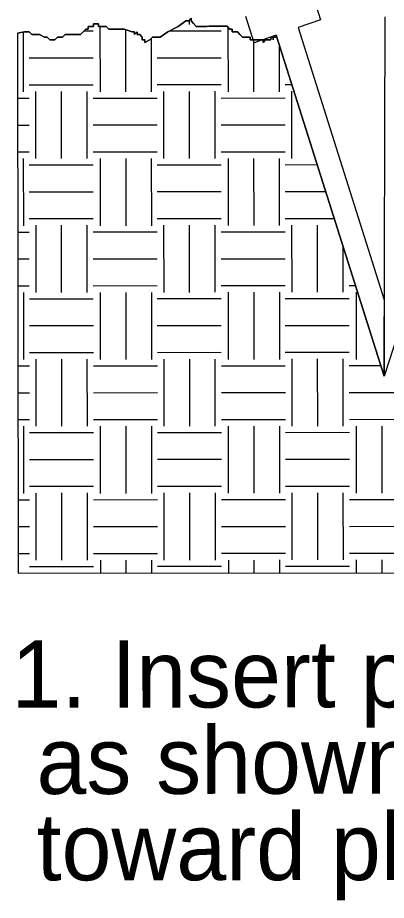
# Model space of a CAD drawing. Extents: x 816132 to 817815, y 885694 to 886789.
# Drawn here: x 816625.1 to 816662, y 886354.3 to 886442.4 of the extents above; entities that cross this region are included whole.
import ezdxf

# ---------------------------------------------------------------- set-up
doc = ezdxf.new("R2010")
doc.units = 0
doc.layers.add('Silt Fence Coir Fiber Wattle Break Detail CELL', color=7, linetype='Continuous')

msp = doc.modelspace()

# ---------------------------------------------------------------- linework, layer by layer
at = {"layer": 'Silt Fence Coir Fiber Wattle Break Detail CELL'}
for p, q in [((816654.546, 886444.801), (816655.377, 886442.179)), ((816648.758, 886439.872), (816647.928, 886442.494)), ((816661.727, 886406.589), (816661.843, 886442.464)), ((816633.353, 886441.513), (816633.358, 886434.979)), ((816642.253, 886442.12), (816642.253, 886441.691)), ((816646.136, 886441.429), (816646.141, 886434.99)), ((816655.377, 886442.179), (816653.15, 886441.403)), ((816625.126, 886440.833), (816625.166, 886386.952)), ((816625.685, 886440.951), (816625.689, 886434.974)), ((816631.755, 886441.059), (816632.667, 886441.059)), ((816635.91, 886441.2), (816635.915, 886434.982)), ((816640.307, 886441.066), (816645.45, 886441.069)), ((816650.951, 886440.637), (816648.758, 886439.872)), ((816661.727, 886406.589), (816650.951, 886440.637)), ((816650.951, 886440.637), (816661.727, 886406.589)), ((816661.727, 886406.589), (816650.951, 886440.637)), ((816653.15, 886441.403), (816661.752, 886414.228)), ((816638.467, 886440.296), (816638.471, 886434.984)), ((816648.693, 886440.179), (816648.697, 886434.992)), ((816651.25, 886439.693), (816651.253, 886434.994)), ((816626.278, 886438.373), (816632.669, 886438.378)), ((816639.06, 886438.383), (816645.451, 886438.389)), ((816626.28, 886435.691), (816632.67, 886435.696)), ((816639.062, 886435.701), (816645.453, 886435.707)), ((816651.845, 886435.712), (816652.51, 886435.712)), ((816626.919, 886435.022), (816626.924, 886428.317)), ((816629.476, 886435.024), (816629.481, 886428.32)), ((816632.032, 886435.025), (816632.037, 886428.322)), ((816632.672, 886434.356), (816639.064, 886434.361)), ((816639.702, 886435.032), (816639.707, 886428.328)), ((816642.258, 886435.033), (816642.263, 886428.33)), ((816644.815, 886435.035), (816644.819, 886428.331)), ((816645.454, 886434.366), (816651.845, 886434.371)), ((816652.484, 886435.041), (816652.489, 886428.338)), ((816625.131, 886434.35), (816626.281, 886434.351)), ((816625.134, 886431.668), (816626.283, 886431.669)), ((816632.674, 886431.674), (816639.065, 886431.679)), ((816645.456, 886431.684), (816651.848, 886431.689)), ((816625.135, 886428.987), (816626.284, 886428.988)), ((816625.693, 886428.317), (816625.698, 886421.612)), ((816632.676, 886428.992), (816639.067, 886428.997)), ((816633.363, 886428.323), (816633.367, 886421.618)), ((816635.919, 886428.325), (816635.924, 886421.62)), ((816638.476, 886428.326), (816638.481, 886421.623)), ((816645.458, 886429.002), (816651.849, 886429.007)), ((816646.145, 886428.333), (816646.15, 886421.628)), ((816648.702, 886428.334), (816648.707, 886421.631)), ((816651.258, 886428.336), (816651.263, 886421.633)), ((816626.286, 886427.693), (816632.677, 886427.698)), ((816639.067, 886427.703), (816645.459, 886427.708)), ((816651.85, 886427.713), (816655.04, 886427.716)), ((816626.288, 886425.012), (816632.678, 886425.017)), ((816639.07, 886425.022), (816645.461, 886425.027)), ((816651.852, 886425.031), (816655.889, 886425.035)), ((816626.289, 886422.33), (816632.681, 886422.335)), ((816639.072, 886422.34), (816645.462, 886422.345)), ((816651.854, 886422.35), (816656.738, 886422.354)), ((816626.929, 886421.661), (816626.933, 886414.956)), ((816629.485, 886421.662), (816629.49, 886414.958)), ((816632.042, 886421.664), (816632.047, 886414.961)), ((816639.711, 886421.67), (816639.716, 886414.966)), ((816642.268, 886421.672), (816642.273, 886414.969)), ((816644.824, 886421.674), (816644.829, 886414.97)), ((816652.494, 886421.68), (816652.499, 886414.977)), ((816655.05, 886421.682), (816655.055, 886414.978)), ((816625.14, 886420.988), (816626.291, 886420.99)), ((816632.681, 886420.995), (816639.073, 886421)), ((816645.464, 886421.005), (816651.855, 886421.01)), ((816657.608, 886419.603), (816657.611, 886414.98)), ((816625.143, 886418.307), (816626.292, 886418.308)), ((816632.683, 886418.313), (816639.075, 886418.318)), ((816645.466, 886418.323), (816651.857, 886418.328)), ((816625.145, 886415.626), (816626.294, 886415.627)), ((816632.686, 886415.631), (816639.076, 886415.636)), ((816645.467, 886415.641), (816651.859, 886415.646)), ((816648.711, 886414.973), (816648.716, 886408.269)), ((816651.268, 886414.975), (816651.272, 886408.272)), ((816658.25, 886415.651), (816658.858, 886415.652)), ((816658.937, 886414.981), (816658.942, 886408.277)), ((816625.703, 886414.956), (816625.707, 886408.251)), ((816626.295, 886414.332), (816632.686, 886414.337)), ((816633.372, 886414.961), (816633.377, 886408.257)), ((816635.929, 886414.964), (816635.933, 886408.259)), ((816638.485, 886414.965), (816638.49, 886408.261)), ((816639.078, 886414.342), (816645.469, 886414.347)), ((816646.155, 886414.972), (816646.159, 886408.267)), ((816651.859, 886414.352), (816658.251, 886414.357)), ((816661.752, 886414.228), (816661.727, 886406.589)), ((816664.068, 886413.823), (816661.727, 886406.589)), ((816664.068, 886413.823), (816661.727, 886406.589)), ((816626.297, 886411.651), (816632.688, 886411.656)), ((816639.079, 886411.661), (816645.47, 886411.666)), ((816651.862, 886411.67), (816658.253, 886411.675)), ((816626.299, 886408.969), (816632.69, 886408.974)), ((816639.081, 886408.979), (816645.472, 886408.984)), ((816651.864, 886408.989), (816658.254, 886408.994)), ((816626.938, 886408.299), (816626.943, 886401.595)), ((816629.495, 886408.301), (816629.499, 886401.597)), ((816632.051, 886408.303), (816632.056, 886401.599)), ((816639.721, 886408.309), (816639.725, 886401.605)), ((816642.277, 886408.311), (816642.282, 886401.607)), ((816644.834, 886408.313), (816644.838, 886401.609)), ((816652.503, 886408.319), (816652.508, 886401.615)), ((816655.06, 886408.321), (816655.064, 886401.617)), ((816657.616, 886408.323), (816657.621, 886401.619)), ((816625.151, 886407.627), (816626.3, 886407.628)), ((816632.691, 886407.633), (816639.083, 886407.638)), ((816645.473, 886407.644), (816651.864, 886407.649)), ((816658.256, 886407.653), (816661.389, 886407.655)), ((816625.152, 886404.945), (816626.302, 886404.946)), ((816632.693, 886404.951), (816639.084, 886404.957)), ((816645.475, 886404.962), (816651.867, 886404.967)), ((816658.257, 886404.972), (816664.649, 886404.976)), ((816625.154, 886402.264), (816626.303, 886402.265)), ((816632.695, 886402.27), (816639.086, 886402.275)), ((816645.478, 886402.28), (816651.868, 886402.285)), ((816658.259, 886402.29), (816664.651, 886402.295)), ((816625.712, 886401.594), (816625.718, 886394.89)), ((816626.305, 886400.971), (816632.696, 886400.976)), ((816633.382, 886401.6), (816633.386, 886394.896)), ((816635.938, 886401.602), (816635.943, 886394.898)), ((816638.495, 886401.604), (816638.499, 886394.9)), ((816639.087, 886400.981), (816645.478, 886400.986)), ((816646.164, 886401.61), (816646.169, 886394.906)), ((816648.721, 886401.612), (816648.725, 886394.908)), ((816651.277, 886401.614), (816651.282, 886394.91)), ((816651.869, 886400.991), (816658.26, 886400.996)), ((816658.947, 886401.62), (816658.951, 886394.916)), ((816661.503, 886401.622), (816661.508, 886394.918)), ((816626.307, 886398.29), (816632.698, 886398.294)), ((816639.089, 886398.3), (816645.48, 886398.305)), ((816651.871, 886398.309), (816658.262, 886398.314)), ((816626.308, 886395.608), (816632.7, 886395.613)), ((816639.091, 886395.618), (816645.482, 886395.623)), ((816651.873, 886395.628), (816658.264, 886395.633)), ((816626.948, 886394.938), (816626.953, 886388.234)), ((816629.504, 886394.94), (816629.51, 886388.236)), ((816632.061, 886394.942), (816632.065, 886388.238)), ((816639.73, 886394.948), (816639.735, 886388.244)), ((816642.287, 886394.95), (816642.291, 886388.246)), ((816644.843, 886394.952), (816644.848, 886388.248)), ((816652.513, 886394.958), (816652.517, 886388.254)), ((816655.069, 886394.96), (816655.074, 886388.256)), ((816657.626, 886394.962), (816657.63, 886388.258)), ((816625.16, 886394.266), (816626.309, 886394.267)), ((816632.7, 886394.272), (816639.092, 886394.277)), ((816645.483, 886394.282), (816651.874, 886394.287)), ((816658.265, 886394.292), (816664.656, 886394.297)), ((816625.162, 886391.584), (816626.311, 886391.585)), ((816632.703, 886391.59), (816639.093, 886391.595)), ((816645.485, 886391.601), (816651.876, 886391.606)), ((816658.267, 886391.611), (816664.659, 886391.615)), ((816625.164, 886388.903), (816626.313, 886388.904)), ((816632.704, 886388.908), (816639.095, 886388.913)), ((816645.487, 886388.919), (816651.878, 886388.924)), ((816658.269, 886388.929), (816664.66, 886388.934)), ((816633.391, 886388.239), (816633.393, 886386.958)), ((816635.948, 886388.241), (816635.949, 886386.96)), ((816638.504, 886388.242), (816638.505, 886386.963)), ((816646.174, 886388.249), (816646.174, 886386.969)), ((816648.73, 886388.25), (816648.731, 886386.971)), ((816651.287, 886388.253), (816651.287, 886386.972)), ((816658.956, 886388.258), (816658.957, 886386.979)), ((816661.513, 886388.261), (816661.513, 886386.98)), ((816625.166, 886386.952), (816701.141, 886387.011)), ((816626.314, 886387.609), (816632.705, 886387.614)), ((816639.097, 886387.62), (816645.488, 886387.625)), ((816651.879, 886387.63), (816658.27, 886387.635))]:
    msp.add_line(p, q, dxfattribs=at)
for points in [[(816625.126, 886440.833), (816625.77, 886440.968), (816626.025, 886440.969), (816626.282, 886440.969), (816626.539, 886440.699), (816626.795, 886440.7), (816627.053, 886440.7), (816627.31, 886440.7), (816627.823, 886440.431), (816628.08, 886440.43), (816628.336, 886440.163), (816628.593, 886440.163), (816628.85, 886440.164), (816629.106, 886440.432), (816629.363, 886440.432), (816629.62, 886440.432), (816629.876, 886440.703), (816630.133, 886440.703), (816630.39, 886440.702), (816630.646, 886440.703), (816630.902, 886440.703), (816631.16, 886440.703), (816631.416, 886440.704), (816631.673, 886440.973), (816631.93, 886441.242), (816632.186, 886441.242), (816632.186, 886441.512), (816632.442, 886441.512), (816632.699, 886441.513), (816632.698, 886441.782), (816632.956, 886441.782), (816633.213, 886441.782), (816633.213, 886441.513), (816633.468, 886441.513), (816633.726, 886441.514), (816633.982, 886441.513), (816634.239, 886441.244), (816634.496, 886441.244), (816634.752, 886441.245), (816635.009, 886441.245), (816635.267, 886441.245), (816635.522, 886441.245), (816635.779, 886441.245), (816636.55, 886440.977), (816636.806, 886440.976), (816636.806, 886440.707), (816637.062, 886440.977), (816637.063, 886440.708), (816637.32, 886440.708), (816637.577, 886440.438), (816637.577, 886440.17), (816637.833, 886440.17), (816637.577, 886440.17), (816637.833, 886440.17), (816637.834, 886439.9), (816638.347, 886440.171), (816638.603, 886440.439), (816638.86, 886440.439), (816639.373, 886440.44), (816640.143, 886440.98), (816641.17, 886441.519), (816641.939, 886442.059), (816642.196, 886442.06), (816642.452, 886442.328), (816642.452, 886442.06), (816642.709, 886441.789), (816642.966, 886441.521), (816643.223, 886441.521), (816643.478, 886441.521), (816643.993, 886441.521), (816644.249, 886441.522), (816644.506, 886441.522), (816645.019, 886441.523), (816645.277, 886441.523), (816645.533, 886441.523), (816646.046, 886441.523), (816646.303, 886441.253), (816646.559, 886441.254), (816646.56, 886440.985), (816646.816, 886440.984), (816647.074, 886440.985), (816647.331, 886440.716), (816647.587, 886440.446), (816647.844, 886440.447), (816648.1, 886440.446), (816648.357, 886440.446), (816648.357, 886440.179), (816648.614, 886440.179), (816648.871, 886440.179), (816649.128, 886440.179), (816649.383, 886440.179), (816649.641, 886440.18), (816649.641, 886439.909), (816649.898, 886440.179), (816650.154, 886440.18), (816650.41, 886440.18), (816650.411, 886440.448), (816650.667, 886440.448), (816650.667, 886440.181), (816650.667, 886440.448), (816650.923, 886440.449)], [(816650.923, 886440.449), (816650.667, 886440.448), (816650.667, 886440.181), (816650.667, 886440.448), (816650.411, 886440.448), (816650.41, 886440.18), (816650.154, 886440.18), (816649.898, 886440.179), (816649.641, 886439.909), (816649.641, 886440.18), (816649.383, 886440.179), (816649.128, 886440.179), (816648.871, 886440.179), (816648.614, 886440.179), (816648.357, 886440.179), (816648.357, 886440.446), (816648.1, 886440.446), (816647.844, 886440.447), (816647.587, 886440.446), (816647.331, 886440.716), (816647.074, 886440.985), (816646.816, 886440.984), (816646.56, 886440.985), (816646.559, 886441.254), (816646.303, 886441.253), (816646.046, 886441.523), (816645.533, 886441.523), (816645.277, 886441.523), (816645.019, 886441.523), (816644.506, 886441.522), (816644.249, 886441.522), (816643.993, 886441.521), (816643.478, 886441.521), (816643.223, 886441.521), (816642.966, 886441.521), (816642.709, 886441.789), (816642.452, 886442.06), (816642.452, 886442.328), (816642.196, 886442.06), (816641.939, 886442.059), (816641.17, 886441.519), (816640.143, 886440.98), (816639.373, 886440.44), (816638.86, 886440.439), (816638.603, 886440.439), (816638.347, 886440.171), (816637.834, 886439.9), (816637.833, 886440.17), (816637.577, 886440.17), (816637.833, 886440.17), (816637.577, 886440.17), (816637.577, 886440.438), (816637.32, 886440.708), (816637.063, 886440.708), (816637.062, 886440.977), (816636.806, 886440.707), (816636.806, 886440.976), (816636.55, 886440.977), (816635.779, 886441.245), (816635.522, 886441.245), (816635.267, 886441.245), (816635.009, 886441.245), (816634.752, 886441.245), (816634.496, 886441.244), (816634.239, 886441.244), (816633.982, 886441.513), (816633.726, 886441.514), (816633.468, 886441.513), (816633.213, 886441.513), (816633.213, 886441.782), (816632.956, 886441.782), (816632.698, 886441.782), (816632.699, 886441.513), (816632.442, 886441.512), (816632.186, 886441.512), (816632.186, 886441.242), (816631.93, 886441.242), (816631.673, 886440.973), (816631.416, 886440.704), (816631.16, 886440.703), (816630.902, 886440.703), (816630.646, 886440.703), (816630.39, 886440.702), (816630.133, 886440.703), (816629.876, 886440.703), (816629.62, 886440.432), (816629.363, 886440.432), (816629.106, 886440.432), (816628.85, 886440.164), (816628.593, 886440.163), (816628.336, 886440.163), (816628.08, 886440.43), (816627.823, 886440.431), (816627.31, 886440.7), (816627.053, 886440.7), (816626.795, 886440.7), (816626.539, 886440.699), (816626.282, 886440.969), (816626.025, 886440.969), (816625.77, 886440.968), (816625.126, 886440.833)]]:
    msp.add_lwpolyline(points, dxfattribs=at)

# ---------------------------------------------------------------- texts
for s, p in [('1. Insert planting bar ', (816624.52, 886373.514)), (' as shown and pull handle ', (816624.527, 886364.894)), (' toward planter.', (816624.533, 886356.274))]:
    msp.add_text(s, height=6.70408, rotation=0.04504, dxfattribs=at).set_placement(p)

doc.saveas('drawing.dxf')
